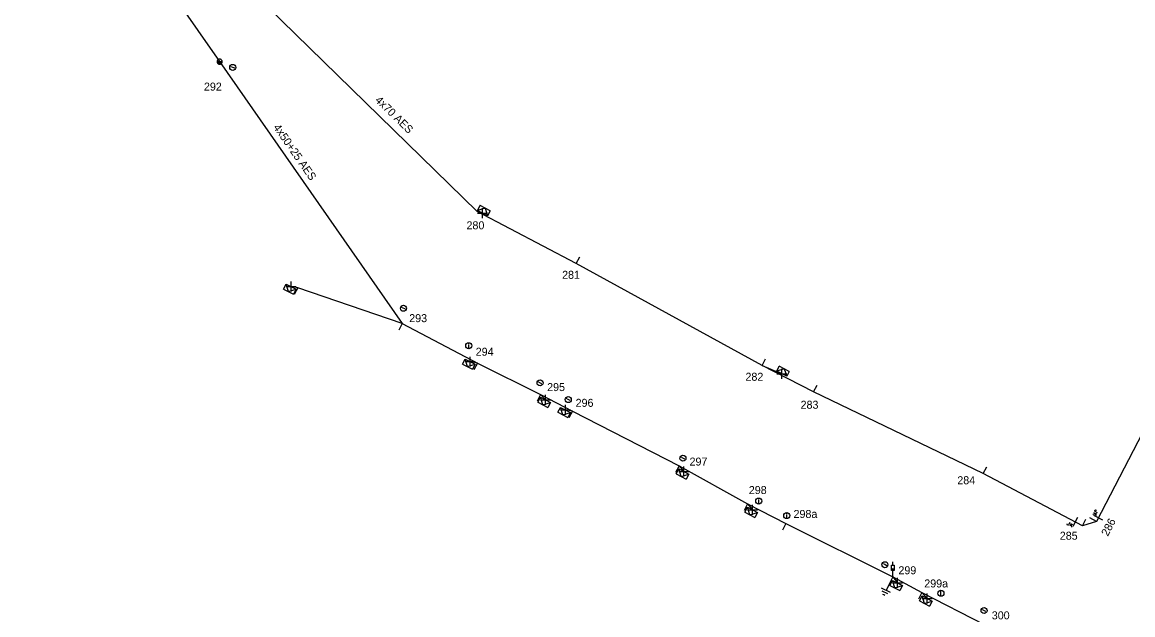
# Model space of a CAD drawing. Extents: x -540466 to -537383, y -1184038 to -1179972.
# Drawn here: x -538071.3 to -537932.4, y -1180719.7 to -1180645.6 of the extents above; entities that cross this region are included whole.
import ezdxf

# ---------------------------------------------------------------- set-up
doc = ezdxf.new("R2010")
doc.units = 0
for name, color, linetype in [('Vrstva 1', 7, 'Continuous'), ('Vrstva 10', 7, 'Continuous'), ('Vrstva 13', 7, 'Continuous'), ('Vrstva 14', 7, 'Continuous'), ('Vrstva 15', 7, 'Continuous'), ('Vrstva 16', 7, 'Continuous'), ('Vrstva 18', 7, 'Continuous'), ('Vrstva 2', 7, 'Continuous'), ('Vrstva 31', 7, 'Continuous'), ('Vrstva 34', 7, 'Continuous'), ('Vrstva 36', 7, 'Continuous'), ('Vrstva 50', 7, 'Continuous'), ('Vrstva 51', 7, 'Continuous'), ('Vrstva 8', 7, 'Continuous'), ('Vrstva 9', 7, 'Continuous')]:
    doc.layers.add(name, color=color, linetype=linetype)

# ---------------------------------------------------------------- blocks, each defined once
blk = doc.blocks.new('NN440')
at = {"layer": 'Vrstva 2'}
for points in [[(0.63, 0), (0.63, 0.06), (0.62, 0.13), (0.6, 0.19), (0.58, 0.25), (0.55, 0.31), (0.51, 0.37), (0.47, 0.42), (0.42, 0.46), (0.37, 0.51), (0.32, 0.54), (0.26, 0.57), (0.2, 0.59), (0.13, 0.61), (0.07, 0.62), (0, 0.63), (-0.06, 0.62), (-0.13, 0.61), (-0.19, 0.59), (-0.26, 0.57), (-0.31, 0.54), (-0.37, 0.51), (-0.42, 0.46), (-0.47, 0.42), (-0.51, 0.37), (-0.54, 0.31), (-0.57, 0.25), (-0.6, 0.19), (-0.62, 0.13), (-0.63, 0.06), (-0.63, 0), (-0.63, -0.07), (-0.62, -0.14), (-0.6, -0.2), (-0.57, -0.26), (-0.54, -0.32), (-0.51, -0.37), (-0.47, -0.43), (-0.42, -0.47), (-0.37, -0.51), (-0.31, -0.55), (-0.26, -0.58), (-0.19, -0.6), (-0.13, -0.62), (-0.06, -0.63), (0, -0.63), (0.07, -0.63), (0.13, -0.62), (0.2, -0.6), (0.26, -0.58), (0.32, -0.55), (0.37, -0.51), (0.42, -0.47), (0.47, -0.43), (0.51, -0.37), (0.55, -0.32), (0.58, -0.26), (0.6, -0.2), (0.62, -0.14), (0.63, -0.07), (0.63, 0)], [(-0.63, 0), (0.63, 0)], [(-0.6, -0.18), (0.57, -0.18)], [(-0.51, -0.32), (0.5, -0.32)], [(-0.37, -0.47), (0.35, -0.47)]]:
    blk.add_lwpolyline(points, dxfattribs=at)
blk = doc.blocks.new('NN840')
at = {"layer": 'Vrstva 15'}
for points in [[(0, 0.62), (0, -0.63)], [(-0.75, -0.71), (-0.75, -0.66)], [(-0.73, -0.76), (-0.75, -0.71)], [(-0.66, -0.8), (-0.73, -0.76)], [(-0.63, -0.8), (-0.66, -0.8)], [(-0.56, -0.76), (-0.63, -0.8)], [(-0.54, -0.71), (-0.56, -0.76)], [(-0.54, -0.38), (-0.54, -0.71)], [(-0.33, -0.38), (-0.33, -0.8)], [(-0.33, -0.64), (-0.13, -0.38)], [(-0.26, -0.56), (-0.09, -0.8)]]:
    blk.add_lwpolyline(points, dxfattribs=at)
blk = doc.blocks.new('NN770')
at = {"layer": 'Vrstva 10'}
for p, q in [((0, 0.19), (0, 0.26)), ((0, -0.28), (0, 0.11))]:
    blk.add_line(p, q, dxfattribs=at)
blk.add_circle((0, -0.01), 0.375, dxfattribs=at)
blk = doc.blocks.new('NN800')
at = {"layer": 'Vrstva 1'}
for points in [[(-0.44, 0.44), (0.44, -0.44)], [(-0.44, -0.44), (0.44, 0.44)]]:
    blk.add_lwpolyline(points, dxfattribs=at)
blk = doc.blocks.new('NN820')
at = {"layer": 'Vrstva 13'}
for points in [[(0, 0), (0, -1.05)], [(-0.16, -0.81), (0.16, -0.81)], [(-0.16, -1.47), (-0.16, -0.81)], [(0, -1.05), (-0.06, -0.93)], [(0, -1.05), (0.06, -0.93)], [(0.16, -0.81), (0.16, -1.47)], [(0.16, -1.47), (-0.16, -1.47)], [(0, -1.47), (0, -1.87)]]:
    blk.add_lwpolyline(points, dxfattribs=at)
blk = doc.blocks.new('NN630')
at = {"layer": 'Vrstva 9'}
for points in [[(0, -0.7), (-0.7, 0)], [(-0.7, -0.7), (-0.7, 0), (0.7, 0), (0.7, -0.7)], [(-0.7, -0.7), (0.7, -0.7)], [(0, -0.7), (0.7, 0)]]:
    blk.add_lwpolyline(points, dxfattribs=at)
blk = doc.blocks.new('NN810')
at = {"layer": 'Vrstva 14'}
for points in [[(0, -0.64), (0, -1.89)], [(0.63, -1.89), (-0.62, -1.89)], [(0.39, -2.2), (-0.4, -2.2)], [(0, -2.52), (-0.12, -2.52)], [(0.14, -2.52), (0, -2.52)]]:
    blk.add_lwpolyline(points, dxfattribs=at)
blk = doc.blocks.new('NN510')
at = {"layer": 'Vrstva 2'}
blk.add_lwpolyline([(0, 0), (0, 0.94)], dxfattribs=at)

msp = doc.modelspace()

# ---------------------------------------------------------------- linework, layer by layer
at = {"layer": 'Vrstva 50'}
for points in [[(-538071.26, -1180615.16), (-538046.58, -1180650.51), (-538023.75, -1180683.26), (-538014.35, -1180688.2), (-538006.46, -1180692.14), (-538002.47, -1180694.22), (-537989.15, -1180701.08), (-537980.6, -1180705.81), (-537975.8, -1180708.29), (-537962.43, -1180714.94), (-537958.79, -1180716.9), (-537951, -1180720.9), (-537950.48, -1180721.17)], [(-537938.74, -1180708.55), (-537951.12, -1180702), (-537972.33, -1180691.82), (-537978.76, -1180688.51), (-538002.01, -1180675.74), (-538014.39, -1180669.26), (-538049.3, -1180635.09), (-538070.71, -1180615.2)], [(-537912.19, -1180624.81), (-537913.48, -1180634.44), (-537917.21, -1180653.27), (-537920.56, -1180670.62), (-537927.21, -1180689.24), (-537936.97, -1180708.01), (-537938.74, -1180708.55)]]:
    msp.add_lwpolyline(points, dxfattribs=at)
at = {"layer": 'Vrstva 8'}
for points in [[(-538014.39, -1180669.26), (-538013.71, -1180669.46)], [(-538023.75, -1180683.26), (-538036.82, -1180678.78), (-538037.64, -1180678.64)], [(-538014.35, -1180688.2), (-538015.27, -1180688.03)], [(-537978.76, -1180688.51), (-537976.32, -1180689.55)], [(-538006.46, -1180692.14), (-538005.84, -1180692.81)], [(-538002.47, -1180694.22), (-538003.36, -1180694.06)], [(-537989.15, -1180701.08), (-537988.56, -1180701.77)], [(-537980.6, -1180705.81), (-537979.98, -1180706.56)], [(-537962.43, -1180714.94), (-537961.86, -1180715.7)], [(-537958.79, -1180716.9), (-537958.14, -1180717.66)]]:
    msp.add_lwpolyline(points, dxfattribs=at)

# ---------------------------------------------------------------- block references
at = {"layer": 'Vrstva 13', "xscale": 0.5, "yscale": 0.5}
msp.add_blockref('NN440', (-538046.58, -1180650.51), dxfattribs=at)
at = {"layer": 'Vrstva 13'}
for p, rotation in [((-538014.39, -1180669.26), -27.5972972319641), ((-538002.01, -1180675.74), -27.597297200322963), ((-538036.82, -1180678.78), 153.1369110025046), ((-538023.75, -1180683.26), 152.37528877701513), ((-538014.35, -1180688.2), 152.37528889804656), ((-537978.76, -1180688.51), -26.85121109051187), ((-537972.33, -1180691.82), -26.851211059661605), ((-538006.46, -1180692.14), 152.54791101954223), ((-538002.47, -1180694.22), 151.99715838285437), ((-537989.15, -1180701.08), 152.51584436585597), ((-537951.12, -1180702), -28.079355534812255), ((-537980.6, -1180705.81), 152.65470549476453), ((-537938.74, -1180708.55), -28.079355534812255), ((-537936.97, -1180708.01), 62.55184728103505), ((-537975.8, -1180708.29), 152.65470552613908), ((-537962.43, -1180714.94), 153.0688944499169), ((-537958.79, -1180716.9), 151.94587219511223)]:
    msp.add_blockref('NN510', p, dxfattribs=dict(at, rotation=rotation))
at = {"layer": 'Vrstva 15', "rotation": -26.42498894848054}
msp.add_blockref('NN810', (-537962.43, -1180714.94), dxfattribs=at)
at = {"layer": 'Vrstva 16', "rotation": 179.9078861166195}
msp.add_blockref('NN820', (-537962.43, -1180714.94), dxfattribs=at)
at = {"layer": 'Vrstva 18'}
for p, rotation in [((-537939.65, -1180708.07), -27.88238333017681), ((-537936.75, -1180707.58), -117.48058055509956)]:
    msp.add_blockref('NN840', p, dxfattribs=dict(at, rotation=rotation))
at = {"layer": 'Vrstva 31'}
for p, rotation in [((-538013.71, -1180669.46), 152.40254726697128), ((-538037.64, -1180678.64), -26.86308899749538), ((-538015.26, -1180688.03), -27.624711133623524), ((-537976.32, -1180689.55), 153.14878894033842), ((-538005.84, -1180692.81), -27.43972779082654), ((-538003.36, -1180694.07), -27.593086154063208), ((-537988.56, -1180701.77), -27.47085564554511), ((-537979.98, -1180706.56), -27.34529438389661), ((-537961.86, -1180715.7), -26.947563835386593), ((-537958.13, -1180717.66), -28.054127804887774)]:
    msp.add_blockref('NN630', p, dxfattribs=dict(at, rotation=rotation))
at = {"layer": 'Vrstva 34'}
for p, rotation in [((-538013.71, -1180669.46), 45), ((-538037.64, -1180678.64), 45), ((-538015.27, -1180688.03), 45), ((-537976.32, -1180689.55), 45), ((-538005.84, -1180692.81), 45), ((-538003.36, -1180694.06), 45), ((-537988.56, -1180701.77), 45.00000009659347), ((-537979.98, -1180706.56), 45), ((-537961.86, -1180715.7), 45), ((-537958.14, -1180717.66), 45)]:
    msp.add_blockref('NN800', p, dxfattribs=dict(at, rotation=rotation))
at = {"layer": 'Vrstva 36'}
for p, rotation in [((-538044.95, -1180651.22), 69.34108890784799), ((-538023.61, -1180681.35), 62.36948611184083), ((-538006.54, -1180690.68), 62.56027224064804), ((-538003.01, -1180692.77), 61.98507785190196), ((-537988.67, -1180700.1), 62.50605831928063), ((-537963.43, -1180713.42), 63.05243610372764), ((-537951.04, -1180719.15), 61.959847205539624)]:
    msp.add_blockref('NN770', p, dxfattribs=dict(at, rotation=rotation))
for p in [(-538015.44, -1180686.03), (-537979.2, -1180705.45), (-537975.69, -1180707.28), (-537956.42, -1180716.99)]:
    msp.add_blockref('NN770', p, dxfattribs=at)

# ---------------------------------------------------------------- texts
at = {"layer": 'Vrstva 14'}
for s, p in [('292', (-538048.54, -1180654.13)), ('280', (-538015.72, -1180671.48)), ('281', (-538003.77, -1180677.67)), ('293', (-538022.88, -1180683.09)), ('294', (-538014.57, -1180687.29)), ('282', (-537980.85, -1180690.42)), ('295', (-538005.64, -1180691.71)), ('296', (-538002.08, -1180693.68)), ('283', (-537973.96, -1180693.92)), ('297', (-537987.84, -1180701.03)), ('298', (-537980.43, -1180704.59)), ('284', (-537954.37, -1180703.36)), ('298a', (-537974.84, -1180707.58)), ('285', (-537941.56, -1180710.3)), ('299', (-537961.73, -1180714.62)), ('299a', (-537958.5, -1180716.27)), ('300', (-537950.06, -1180720.26))]:
    msp.add_text(s, height=1, dxfattribs=at).set_placement(p)
msp.add_text('286', height=1, rotation=62.552, dxfattribs=at).set_placement((-537935.55, -1180709.94))
at = {"layer": 'Vrstva 51'}
for s, rotation, p in [('4x70 AES', 315.61, (-538027.22, -1180655.42)), ('4x50+25 AES', 304.882, (-538039.93, -1180658.73))]:
    msp.add_text(s, height=1, rotation=rotation, dxfattribs=at).set_placement(p)

doc.saveas('drawing.dxf')
